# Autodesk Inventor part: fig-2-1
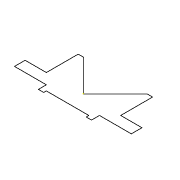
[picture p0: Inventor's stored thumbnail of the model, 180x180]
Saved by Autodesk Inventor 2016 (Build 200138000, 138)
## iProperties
Created: 2011-06
Part Number: fig-2-1
Material: Generic
Document SubType Name: Modeling
Designer: CadCim
Density: 1 g/cm^3
Appearance: Default
Author: CadCim
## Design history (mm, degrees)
sketch "Sketch1"
  geometry: L1 (0, 0)-(-3, 3); L2 (-2, -1.5)-(2, -1.5); L3 (3, 3)-(0, 0); L4 (3.5, 3)-(3, 3); L5 (3.5, 0)-(3.5, 3); L6 (2, -1.75)-(2.5, -1.75); L7 (2.5, -1.75)-(2.5, -1); L8 (5.5, 0)-(3.5, 0); L9 (5.5, -1)-(5.5, 0); L10 (2.5, -1)-(5.5, -1); L11 (2, -1.5)-(2, -1.75); L12 (-3, 3)-(-3.5, 3); L13 (-2, -1.75)-(-2, -1.5); L14 (-2.5, -1.75)-(-2, -1.75); L15 (-2.5, -1)-(-2.5, -1.75); L16 (-5.5, -1)-(-2.5, -1); L17 (-5.5, 0)-(-5.5, -1); L18 (-3.5, 0)-(-5.5, 0); L19 (-3.5, 3)-(-3.5, 0); 1 further point
  constraints: 38 end point, 17 perpendicular, 1 horizontal
